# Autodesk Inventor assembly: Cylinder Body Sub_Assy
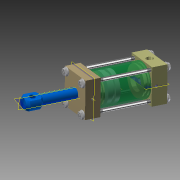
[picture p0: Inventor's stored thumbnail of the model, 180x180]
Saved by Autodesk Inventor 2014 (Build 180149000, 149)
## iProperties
Created: 2008-07
Part Number: Cylinder Body Sub_Assy
Document SubType Name: Assembly
Designer: normanpa
Mass: 1245.04 g
Surface Area: 688.692 cm^2
Volume: 165.976 cm^3
Density: 7.50134 g/cm^3
Author: normanpa
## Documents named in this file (10)
- C:\Users\iTools\Desktop\tutorial files\Cylinder Clamp\Cylinder Body Sub_Assy.iam
- C:\Users\iTools\Desktop\tutorial files\Cylinder Clamp\Cylinder Head Cover_Front.ipt
- C:\Users\iTools\Desktop\tutorial files\Cylinder Clamp\Cylinder Body.ipt
- C:\Users\iTools\Desktop\tutorial files\Cylinder Clamp\Cylinder Head Cover_Back.ipt
- C:\Users\iTools\Desktop\tutorial files\Cylinder Clamp\M5 Threaded Rod.ipt
- C:\Users\iTools\Desktop\tutorial files\Cylinder Clamp\ANSI B18.2.4.4M - M5 x 0.8.ipt
- C:\Users\iTools\Desktop\tutorial files\Cylinder Clamp\Piston Rod.ipt
- C:\Users\iTools\Desktop\tutorial files\Cylinder Clamp\Piston.ipt
- C:\Users\iTools\Desktop\tutorial files\Cylinder Clamp\AS 1969 - M8(1).ipt
- C:\Users\iTools\Desktop\tutorial files\Cylinder Clamp\ANSI B18.2.4.2M - M8x1.25 - 13.ipt
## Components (19 placed, 9 different names)
1. Cylinder Head Cover_Front:1 — Insert:1, Flush:1, Mate:1, Flush:2, Insert:3, Mate:2
2. Cylinder Body:1 — Insert:1, Insert:2
3. Cylinder Head Cover_Back:1 — Insert:2, Flush:1, Insert:4, Mate:3
4. Piston Rod:1 — Insert:5, Mate:2
5. Piston:1 — Insert:5, Insert:6, Mate:3
6. AS 1969 (External Tooth Lock Washer Type A) M8:1 — Insert:6, Insert:7
7. ANSI B18.2.4.2M M8x1.25:1 — Insert:7
8. M5 Threaded Rod:1 — Mate:1, Flush:2
9. Metric Hex Flange Nuts - Metric M5 x 0.8:1 — Insert:3
10. Metric Hex Flange Nuts - Metric M5 x 0.8:2 — Insert:4
11. M5 Threaded Rod:2
12. Metric Hex Flange Nuts - Metric M5 x 0.8:3
13. Metric Hex Flange Nuts - Metric M5 x 0.8:4
14. M5 Threaded Rod:3
15. Metric Hex Flange Nuts - Metric M5 x 0.8:5
16. Metric Hex Flange Nuts - Metric M5 x 0.8:6
17. M5 Threaded Rod:4
18. Metric Hex Flange Nuts - Metric M5 x 0.8:7
19. Metric Hex Flange Nuts - Metric M5 x 0.8:8
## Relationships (12: Insert 7, Mate 3, Flush 2)
- Insert:1: Cylinder Head Cover_Front:1 ↔ Cylinder Body:1
- Insert:2: Cylinder Body:1 ↔ Cylinder Head Cover_Back:1
- Flush:1: Cylinder Head Cover_Front:1 ↔ Cylinder Head Cover_Back:1
- Mate:1: Cylinder Head Cover_Front:1 ↔ M5 Threaded Rod:1
- Flush:2: Cylinder Head Cover_Front:1 ↔ M5 Threaded Rod:1
- Insert:3: Cylinder Head Cover_Front:1 ↔ Metric Hex Flange Nuts - Metric M5 x 0.8:1
- Insert:4: Cylinder Head Cover_Back:1 ↔ Metric Hex Flange Nuts - Metric M5 x 0.8:2
- Insert:5: Piston Rod:1 ↔ Piston:1
- Insert:6: Piston:1 ↔ AS 1969 (External Tooth Lock Washer Type A) M8:1
- Insert:7: AS 1969 (External Tooth Lock Washer Type A) M8:1 ↔ ANSI B18.2.4.2M M8x1.25:1
- Mate:2: Cylinder Head Cover_Front:1 ↔ Piston Rod:1
- Mate:3: Cylinder Head Cover_Back:1 ↔ Piston:1
